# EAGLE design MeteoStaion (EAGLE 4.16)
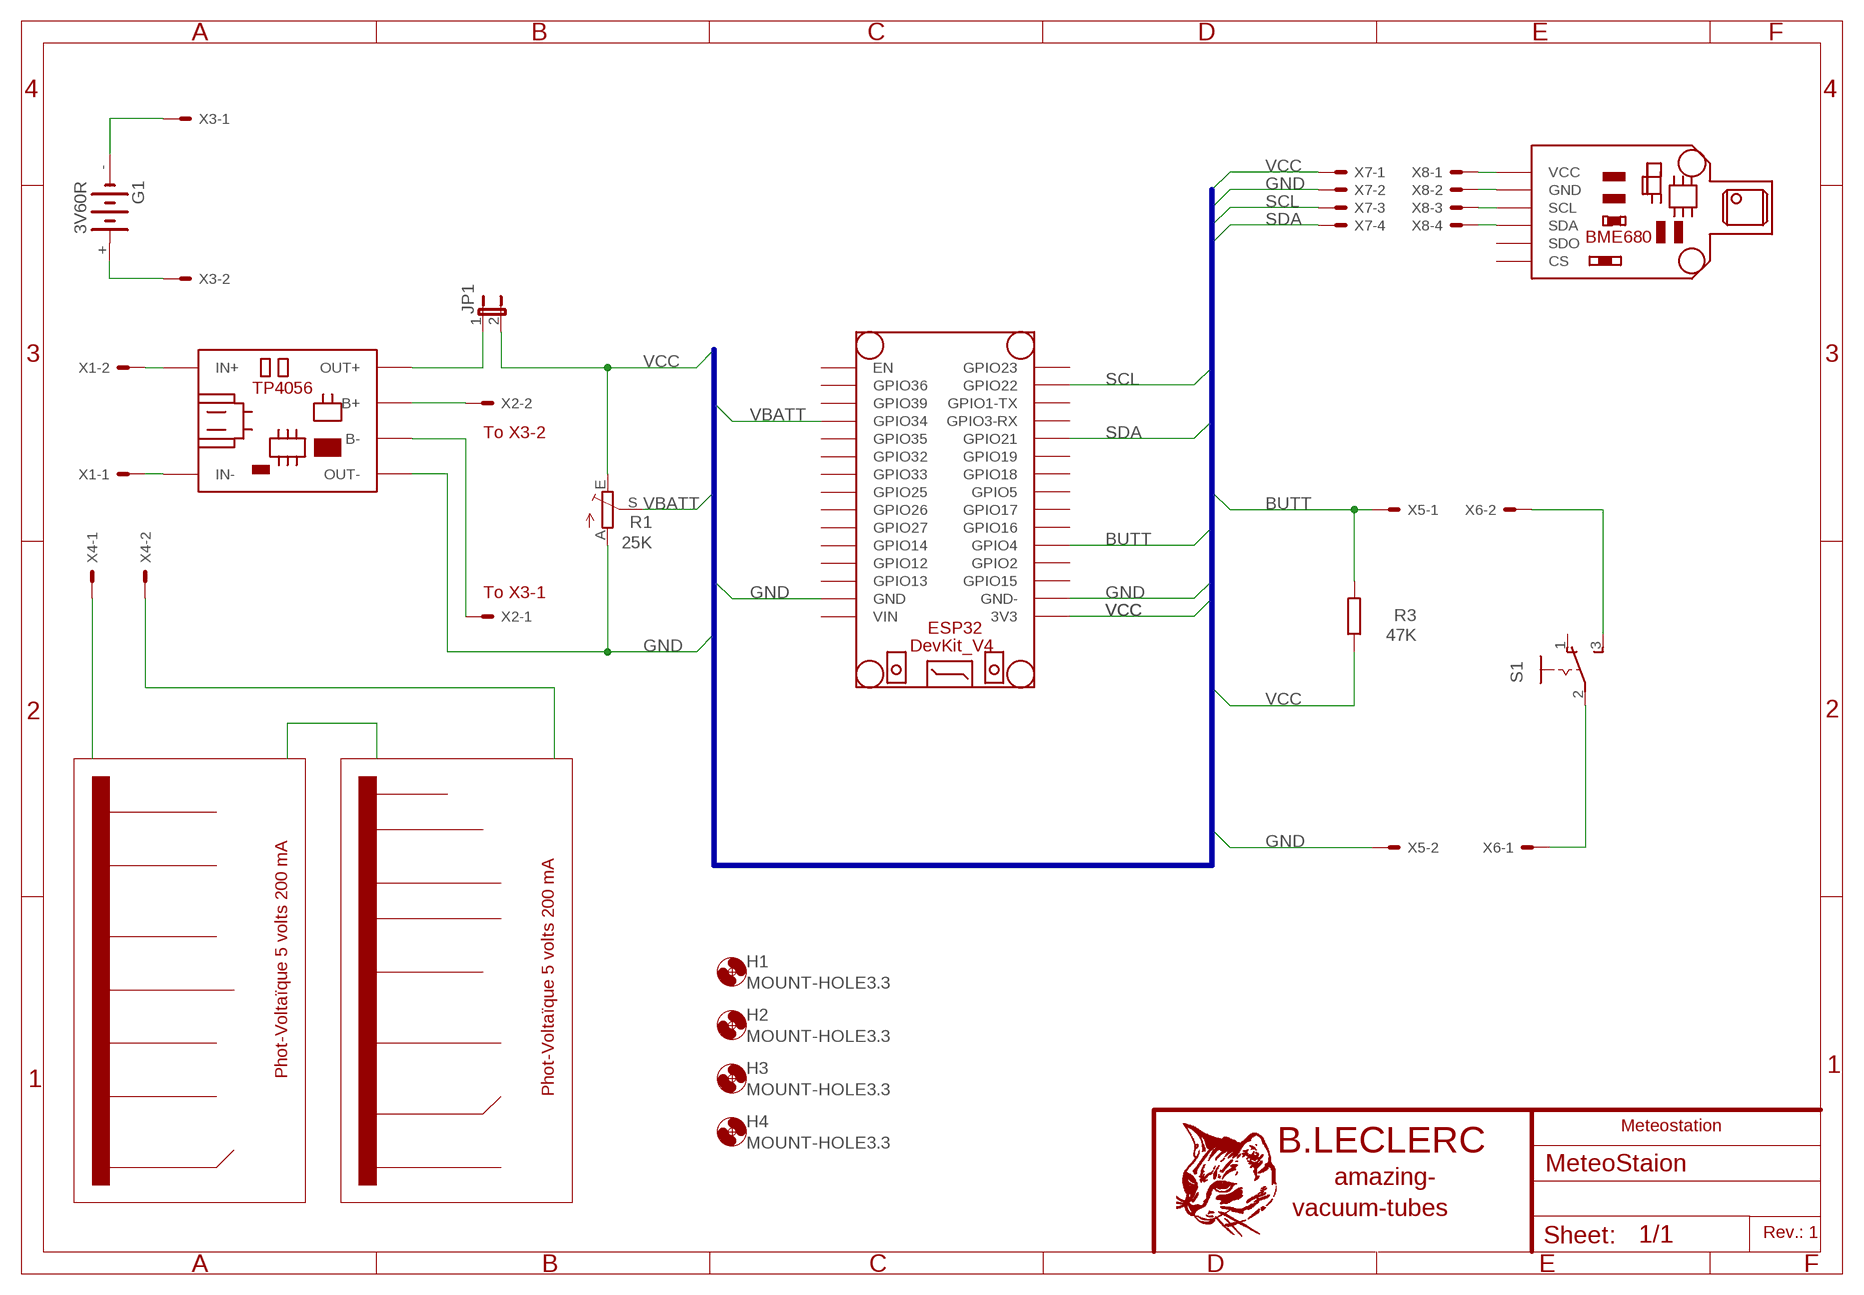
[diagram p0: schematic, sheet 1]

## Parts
G1  3V60R  [3V60R]
H1  MOUNT-HOLE3.3  [3,3]
H2  MOUNT-HOLE3.3  [3,3]
H3  MOUNT-HOLE3.3  [3,3]
H4  MOUNT-HOLE3.3  [3,3]
JP1  JP1E  [JP1]
R1  25K  TRIM_EU-B64Y  [B64Y]
R3  47K  R-EU_M1206  [M1206]
S1  255SB  [255SB]
U$2  ESP32  [ESP32]
U$3  BME680  [BME680]
U$4  CHARGEUR_ION-LI  [CHARGEUR_ION-LI]
X1  22-23-2021  [22-23-2021]
X2  22-23-2021  [22-23-2021]
X3  22-23-2021  [22-23-2021]
X4  22-23-2021  [22-23-2021]
X5  22-23-2021  [22-23-2021]
X6  22-23-2021  [22-23-2021]
X7  22-23-2041  [22-23-2041]
X8  22-23-2041  [22-23-2041]

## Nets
BUTT: R3.2 U$2.GPIO4 X5.1
GND: R1.A U$2.GND U$2.GND- U$4.OUT- X5.2 X7.2
N$1: U$4.B+ X2.2
N$2: U$4.B- X2.1
N$3: G1.+ X3.2
N$4: G1.- X3.1
N$5: U$4.IN+ X1.2
N$6: U$4.IN- X1.1
N$7: X4.1
N$8: X4.2
N$10: S1.3(S) X6.2
N$11: S1.2(P) X6.1
N$12: U$3.VCC X8.1
N$13: U$3.GND X8.2
N$14: U$3.SCL X8.3
N$15: U$3.SDA X8.4
N$24: JP1.1 U$4.OUT+
SCL: U$2.GPIO22 X7.3
SDA: U$2.GPIO21 X7.4
VBATT: R1.S U$2.GPIO34
VCC: JP1.2 R1.E R3.1 U$2.3V3 X7.1
Unconnected: G1.+@1(+) S1.1(O) U$2.EN U$2.GPIO1-TX U$2.GPIO2 U$2.GPIO3-RX U$2.GPIO5 U$2.GPIO12 U$2.GPIO13 U$2.GPIO14 U$2.GPIO15 U$2.GPIO16 U$2.GPIO17 U$2.GPIO18 U$2.GPIO19 U$2.GPIO23 U$2.GPIO25 U$2.GPIO26 U$2.GPIO27 U$2.GPIO32 U$2.GPIO33 U$2.GPIO35 U$2.GPIO36 U$2.GPIO39 U$3.CS U$3.SDO

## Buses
B$1

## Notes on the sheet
- To X3-2
- To X3-1
- Phot-Voltaïque 5 volts 200 mA
- Phot-Voltaïque 5 volts 200 mA
- Meteostation
- Rev.: 1

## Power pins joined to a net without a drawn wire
VIN: U$2.VIN

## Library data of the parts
G1 = battery:3V60R: NC ACCU Varta
H1-H4 = holes:MOUNT-HOLE: MOUNTING HOLE with drill center marker
JP1 = jumper:JP1E: JUMPER
R1 = pot:TRIM_EU-: POTENTIOMETER
R3 = rcl:R-EU_: RESISTOR, European symbol
S1 = switch:255SB: SLIDING SWITCH distributor Buerklin, 11G810
U$2 = Arduino:ESP32
U$3 = Arduino:BME680
U$4 = Arduino:CHARGEUR_ION-LI
X1-X6 = con-molex:22-23-2021: .100" (2.54mm) Center Header - 2 Pin
X7 X8 = con-molex:22-23-2041: .100" (2.54mm) Center Header - 4 Pin

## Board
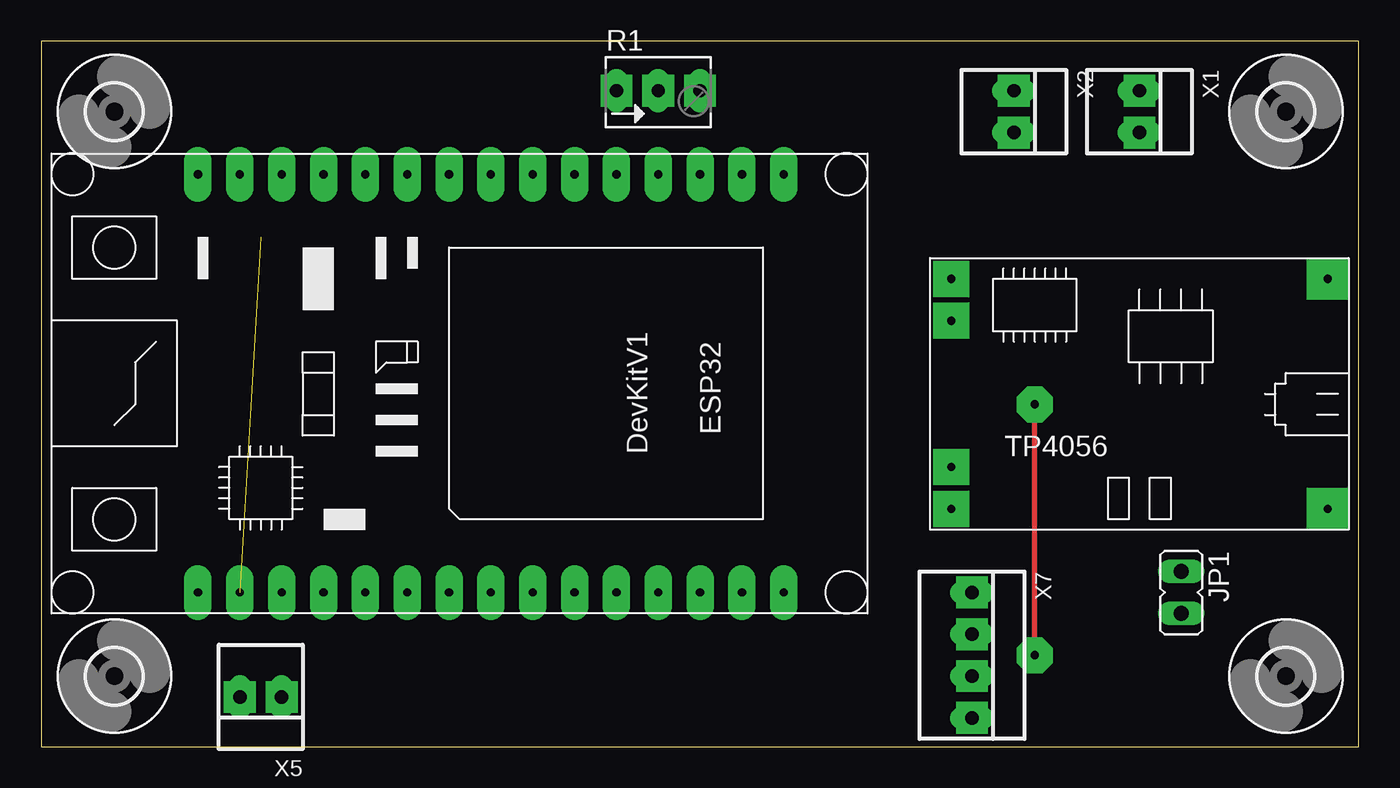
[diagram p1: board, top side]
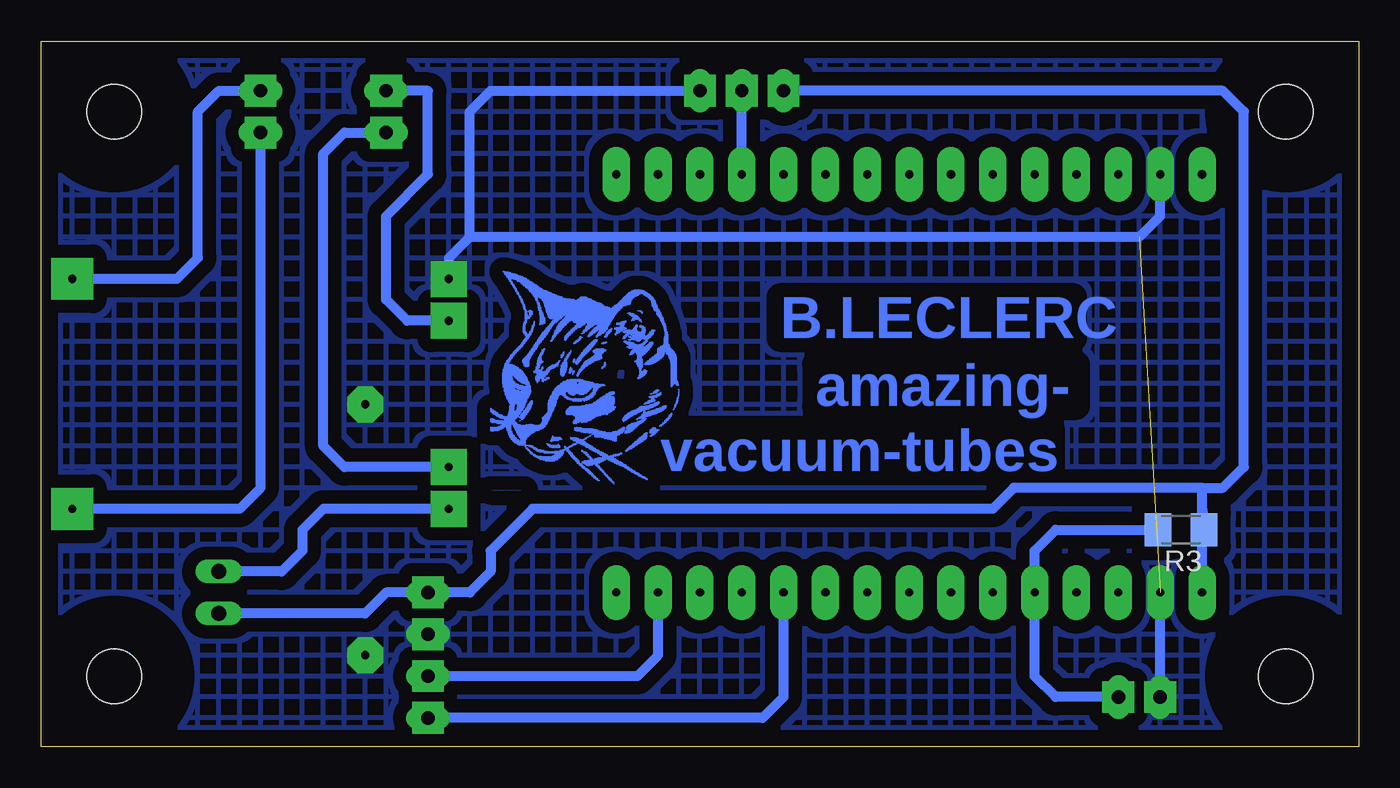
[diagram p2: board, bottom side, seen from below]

Size 79.99 x 42.85 mm. Coordinates in mm from the lower left corner, seen from the top.
Outline: 0,0 79.99,0 79.99,42.85 0,42.85 0,0
Copper layers (1*16): Top 0.035mm / dielectric 1.5mm / Bottom 0.035mm
Design rules "default": minimum track width 10mil, minimum drill 24mil, track to track 8mil, track to pad 8mil, pad to pad 8mil, via to via 8mil, smd to smd 8mil, copper to edge 40mil, drill to drill 8mil, minimum pad ring 10mil, minimum via ring 8mil, stop-mask expansion 4mil, vias tented up to drill 0mil, thermal gap 10mil

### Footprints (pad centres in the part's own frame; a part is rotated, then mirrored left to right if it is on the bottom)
3V60R = drill 1.321 pad 3.15 octagon: + -10.16,-5.08; +@1 -10.16,5.08; - 9.271,0
3,3 = hole 3.3: 0,0
JP1 = drill 0.914 long: 1 0,-1.27; 2 0,1.27
B64Y = drill 0.813 long: A 2.54,0; E -2.54,0; S 0,0
M1206 = smd 1.6 x 2: 1 -1.4,0; 2 1.4,0
255SB = drill 1.118 long: 1 -3.81,0; 2 0,0; 3 3.81,0
ESP32 = drill 0.5 pad 1.676 long: 3V3 12.7,-15.24; EN -12.7,20.32; GND -12.7,-12.7; GND- 12.7,-12.7; GPIO1-TX 12.7,15.24; GPIO2 12.7,-7.62; GPIO3-RX 12.7,12.7; GPIO4 12.7,-5.08; GPIO5 12.7,2.54; GPIO12 -12.7,-7.62; GPIO13 -12.7,-10.16; GPIO14 -12.7,-5.08; GPIO15 12.7,-10.16; GPIO16 12.7,-2.54; GPIO17 12.7,0; GPIO18 12.7,5.08; GPIO19 12.7,7.62; GPIO21 12.7,10.16; GPIO22 12.7,17.78; GPIO23 12.7,20.32; GPIO25 -12.7,2.54; GPIO26 -12.7,0; GPIO27 -12.7,-2.54; GPIO32 -12.7,7.62; GPIO33 -12.7,5.08; GPIO34 -12.7,12.7; GPIO35 -12.7,10.16; GPIO36 -12.7,17.78; GPIO39 -12.7,15.24; VIN -12.7,-15.24
BME680 = drill 0.5 pad 1.778 long: CS 0,-6.35; GND 0,3.81; SCL 0,1.27; SDA 0,-1.27; SDO 0,-3.81; VCC 0,6.35
CHARGEUR_ION-LI = drill 0.5 pad 2.184 square: B+ 24.13,12.7; B- 24.13,3.81; OUT+ 24.13,15.24; OUT- 24.13,1.27 | drill 0.5 pad 2.54 square: IN+ 1.27,15.24; IN- 1.27,1.27
22-23-2021 = drill 0.813 long: 1 -1.27,0; 2 1.27,0
22-23-2041 = drill 0.813 long: 1 -3.81,0; 2 -1.27,0; 3 1.27,0; 4 3.81,0

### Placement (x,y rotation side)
G1  not placed on the board
H1  75.56,38.57 0 top
H2  4.44,4.28 0 top
H3  4.44,38.57 0 top
H4  75.56,4.28 0 top
JP1  69.21,9.36 180 top
R1  37.46,39.84 0 top
R3  10.79,13.17 180 bottom
S1  not placed on the board
U$2  24.76,22.06 270 top
U$3  not placed on the board
U$4  79.37,29.68 180 top
U$5  [CHAT1]  52.7,15.71 0 bottom
X1  66.67,38.57 270 top
X2  59.05,38.57 270 top
X3  not placed on the board
X4  not placed on the board
X5  13.33,3.01 180 top
X6  not placed on the board
X7  56.51,5.55 270 top
X8  not placed on the board

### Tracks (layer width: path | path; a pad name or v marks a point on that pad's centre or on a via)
BUTT
  Bottom 0.61: R3.2 18.41,13.17 19.68,11.9 U$2.GPIO4 19.68,4.28 18.41,3.01 X5.1
GND  (via drill 0.5 pad 1.93, 0.5 pad 2.18)  (1 unrouted)
  Top 0.305: v60.32,5.55 v60.32,20.79
  Bottom 0.61: X5.2 U$2.GND- | U$2.GND 12.06,32.22 13.33,30.95 53.97,30.95 | 53.97,30.95 55.24,29.68 U$4.OUT- | R1.A 52.7,39.84 53.97,38.57 53.97,30.95
  other vias: 56.51,6.82 12.06,3.01
  pour Bottom (isolate 0.813, no thermals, hatched): 0.63,42.38 79.37,42.38 79.37,0.47 0.63,0.47
N$1
  Bottom 0.61: U$4.B+ 61.59,16.98 62.86,18.25 62.86,36.03 61.59,37.3 X2.2
N$2
  Bottom 0.61: X2.1 56.51,39.84 56.51,34.76 59.05,32.22 59.05,27.14 57.78,25.87 U$4.B-
N$3  (1 unrouted)
N$4  (1 unrouted)
N$5
  Bottom 0.61: X1.2 66.67,15.71 67.94,14.44 U$4.IN+
N$6
  Bottom 0.61: X1.1 69.21,39.84 70.48,38.57 70.48,29.68 71.75,28.41 U$4.IN-
N$10  (1 unrouted)
N$11  (1 unrouted)
N$12  (1 unrouted)
N$13  (1 unrouted)
N$14  (1 unrouted)
N$15  (1 unrouted)
N$16  (via drill 0.5 pad 1.93)
  other vias: 66.67,39.84
N$17  (via drill 0.5 pad 1.93)
  other vias: 66.67,37.3
N$18  (via drill 0.5 pad 1.93)
  other vias: 59.05,39.84
N$19  (via drill 0.5 pad 1.93)
  other vias: 59.05,37.3
N$20  (via drill 0.5 pad 1.93)
  other vias: 34.92,39.84
N$21  (via drill 0.5 pad 1.93)
  other vias: 37.46,39.84
N$22  (via drill 0.5 pad 1.93)
  other vias: 40,39.84
N$23  (via drill 0.5 pad 1.93)
  other vias: 56.51,9.36
N$24
  Bottom 0.61: U$4.OUT+ 62.86,14.44 64.13,13.17 64.13,11.9 65.4,10.63 JP1.1
N$25  (via drill 0.5 pad 1.93)
  other vias: 56.51,4.28
N$26  (via drill 0.5 pad 1.93)
  other vias: 56.51,1.74
N$28  (via drill 0.5 pad 1.93)
  other vias: 14.6,3.01
SCL
  Bottom 0.61: U$2.GPIO22 42.54,5.55 43.81,4.28 X7.3
SDA
  Bottom 0.61: U$2.GPIO21 34.92,3.01 36.19,1.74 X7.4
VBATT
  Bottom 0.61: U$2.GPIO34 R1.S
VCC
  Bottom 0.61: U$2.3V3 9.52,14.44 | 9.52,15.71 20.95,15.71 22.22,14.44 50.16,14.44 52.7,11.9 52.7,10.63 53.97,9.36 X7.1 59.05,9.36 60.32,8.09 JP1.2 | 9.52,14.44 R3.1 | 9.52,14.44 9.52,15.71 | R1.E 8.25,39.84 6.98,38.57 6.98,16.98 8.25,15.71 9.52,15.71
